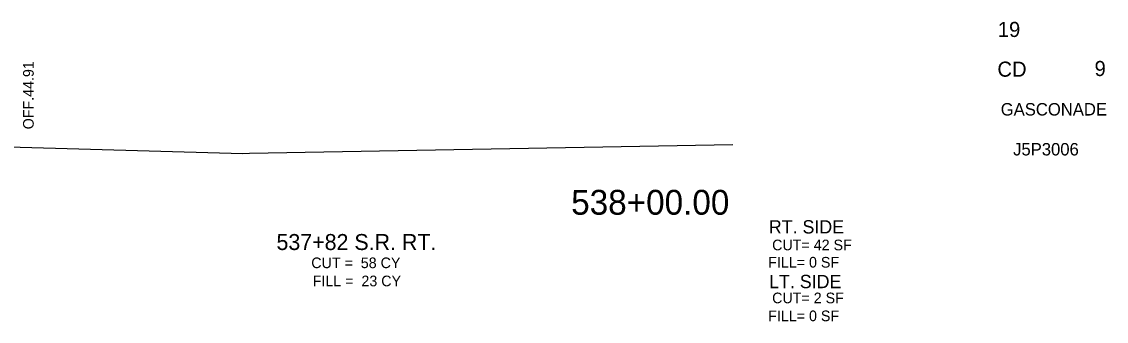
# Model space of a CAD drawing. Extents: x -4 to 359, y 0 to 1436.
# Drawn here: x 93.1 to 154.2, y 1269.2 to 1286.1 of the extents above; entities that cross this region are included whole.
import ezdxf

# ---------------------------------------------------------------- set-up
doc = ezdxf.new("R2010")
doc.units = 0
for name, color, linetype in [('Common-Title block info', 7, 'Continuous'), ('XS-Existing surface-ground', 7, 'Continuous'), ('XS-Text-earthwork labels', 7, 'Continuous'), ('XS-Text-offset label', 7, 'Continuous'), ('XS-Text-tie elevation', 7, 'Continuous')]:
    doc.layers.add(name, color=color, linetype=linetype)

msp = doc.modelspace()

# ---------------------------------------------------------------- linework, layer by layer
at = {"layer": 'XS-Existing surface-ground'}
for p, q in [((92.366, 1279.008), (104.908, 1278.648)), ((105.935, 1278.649), (133.13, 1279.128)), ((104.908, 1278.648), (105.569, 1278.622)), ((105.569, 1278.622), (105.935, 1278.649))]:
    msp.add_line(p, q, dxfattribs=at)

# ---------------------------------------------------------------- texts
at = {"layer": 'Common-Title block info'}
for s, height, p in [('19', 0.85, (148.047, 1285.19)), ('CD', 0.85, (148.025, 1282.952)), ('9', 0.85, (153.492, 1282.988)), ('GASCONADE', 0.7, (148.211, 1280.765)), ('J5P3006', 0.7, (148.909, 1278.515))]:
    msp.add_text(s, height=height, dxfattribs=at).set_placement(p)
at = {"layer": 'XS-Text-earthwork labels'}
for s, height, p in [('RT. SIDE', 0.75, (135.161, 1274.118)), ('537+82 S.R. RT.', 0.9, (107.455, 1273.187)), (' CUT= 42 SF           ', 0.6, (135.125, 1273.171)), ('CUT =  58 CY           ', 0.6, (109.413, 1272.165)), ('FILL= 0 SF           ', 0.6, (135.125, 1272.197)), ('FILL =  23 CY           ', 0.6, (109.492, 1271.143)), ('LT. SIDE', 0.75, (135.176, 1271.037)), (' CUT= 2 SF           ', 0.6, (135.125, 1270.187)), ('FILL= 0 SF           ', 0.6, (135.125, 1269.177))]:
    msp.add_text(s, height=height, dxfattribs=at).set_placement(p)
at = {"layer": 'XS-Text-offset label'}
msp.add_text('           538+00.00           ', height=1.4, dxfattribs=at).set_placement((118.317, 1275.176))
at = {"layer": 'XS-Text-tie elevation'}
msp.add_text('OFF.44.91', height=0.6, rotation=90, dxfattribs=at).set_placement((93.793, 1279.989))

doc.saveas('drawing.dxf')
